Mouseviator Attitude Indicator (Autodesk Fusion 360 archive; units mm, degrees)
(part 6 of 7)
sketch "G1000" plane through (0, 0, 0) normal (0, 1, 0) x axis (1, 0, 0)
  line L1 (-258.3202, -84.4862) -> (-258.3202, -5.9899)
  line L2 (22.9166, -438.2961) -> (-83.2245, -438.2961)
  line L3 (113.9758, -58.4699) -> (-45.0242, -58.4699)
  line L4 (113.9758, -100.0333) -> (-45.0242, -100.0333)
  line L5 (500.0011, -95.2463) -> (-500.7967, -95.2463)
  curve K1 (500.0011, -306.3841) -> (185.0575, -438.1167)
  line L6 (200.3781, -200.5497) -> (-194.6385, -200.5497)
  line L7 (-194.6385, -95.2463) -> (-194.6385, -200.5497)
  line L8 (113.3594, -121.568) -> (109.2085, -117.4156)
  line L9 (-194.6385, -171.4463) -> (-266.0078, -171.4463)
  line L10 (-439.2563, -298.2055) -> (-439.2563, -260.1644)
  line L11 (-298.7965, -191.8326) -> (-387.2573, -191.8326)
  line L12 (-83.2245, -438.2961) -> (-183.5312, -438.2956)
  line L13 (-357.5866, -422.3558) -> (-360.6417, -421.6832)
  line L14 (113.9758, -58.4699) -> (113.9758, -100.0333)
  curve K2 (-183.5312, -438.2956) -> (-357.5866, -422.3558)
  line L15 (-464.0205, -260.1644) -> (-464.0205, -191.8326)
  line L16 (-279.0974, -84.4862) -> (-400.7939, -84.4862)
  line L17 (115.7849, -0.0004) -> (498.5011, -0.0004)
  line L18 (-266.0078, -171.4463) -> (-266.0078, -95.2463)
  line L19 (-258.3202, -5.9899) -> (-134.2963, -5.9899)
  line L20 (-400.7939, -5.9899) -> (-279.0974, -5.9899)
  line L21 (-134.2963, -84.4862) -> (-258.3202, -84.4862)
  line L22 (500.0011, -94.3924) -> (500.0011, -306.3841)
  line L23 (270.459, -171.4463) -> (200.3781, -171.4463)
  line L24 (-500.0066, -306.3725) -> (-500.0051, -94.4039)
  line L25 (-498.5077, 0.0037) -> (-115.1335, 0.0037)
  line L26 (-115.1335, -95.2463) -> (-115.1335, 0.0037)
  line L27 (-387.2573, -191.8326) -> (-387.2573, -260.1644)
  line L28 (-387.2573, -260.1644) -> (-387.2573, -298.2055)
  line L29 (-134.2963, -5.9899) -> (-134.2963, -84.4862)
  line L30 (-279.0974, -5.9899) -> (-279.0974, -84.4862)
  line L31 (-45.0242, -58.4699) -> (-45.0242, -100.0333)
  line L32 (200.3781, -95.2463) -> (200.3781, -200.5497)
  line L33 (-298.7965, -115.6858) -> (-298.7965, -191.8326)
  line L34 (185.0575, -438.1167) -> (22.9358, -438.2967)
  line L35 (-387.2573, -298.2055) -> (-439.2563, -298.2055)
  line L36 (270.459, -95.2463) -> (270.459, -171.4463)
  line L37 (-464.0205, -191.8326) -> (-464.0205, -115.6858)
  line L38 (-464.0205, -115.6858) -> (-298.7965, -115.6858)
  curve K3 (-360.6417, -421.6832) -> (-500.0066, -306.3725)
  line L39 (-439.2563, -260.1644) -> (-464.0205, -260.1644)
  line L40 (500.0011, -1.5017) -> (500.0011, -94.3924)
  line L41 (-500.0053, -91.3773) -> (-500.0076, -1.4963)
  line L42 (22.9358, -438.2967) -> (22.9166, -438.2961)
  line L43 (-121.7047, -438.2959) -> (-83.2245, -438.2961)
  line L44 (106.9943, -127.9308) -> (102.8434, -123.7784)
  line L45 (-400.7939, -84.4862) -> (-400.7939, -5.9899)
  line L46 (367.0685, -437.5413) -> (363.2394, -438.1232)
  line L47 (238.074, -152.3963) -> (238.074, -137.3483)
  line L48 (231.724, -137.3483) -> (231.724, -152.3963)
  line L49 (249.5325, -194.5335) -> (220.2654, -148.3591)
  line L50 (250.2362, -148.8204) -> (219.5617, -194.0721)
  line L51 (-227.2728, -171.4463) -> (-227.2728, -137.3483)
  line L52 (-233.6228, -137.3483) -> (-233.6228, -171.4463)
  line L53 (-215.8142, -194.5335) -> (-245.0814, -148.3591)
  line L54 (-215.1106, -148.8204) -> (-245.785, -194.0721)
  line L55 (115.7842, 0) -> (-115.7842, 0)
  line L56 (0, 20) -> (-69.9424, 20)
  curve K4 (-69.9424, 20) -> (-107.8843, 0)
  curve K5 (-104.8876, -0.1472) -> (-110.8811, 0.1472)
  curve K6 (-65.1162, 20) -> (-74.7686, 20)
  curve K7 (69.9424, 20) -> (107.8843, 0)
  curve K8 (104.8876, -0.1472) -> (110.8811, 0.1472)
  curve K9 (65.1162, 20) -> (74.7686, 20)
  line L57 (0, 20) -> (69.9424, 20)
  line L58 (-107.8843, 0) -> (-115.1335, 0.0037)
  line L59 (137.0775, -0.0004) -> (107.8843, 0)
  arc A1 centre (-269.8771, -5.9899) radius 2.1 clockwise from (-267.7771, -5.9899) to (-269.8771, -8.0899)
  arc A2 centre (-269.8771, -5.9899) radius 2.1 clockwise from (-271.9771, -5.9899) to (-269.8771, -3.8899)
  arc A3 centre (-269.8771, -5.9899) radius 2.1 clockwise from (-269.8771, -8.0899) to (-271.9771, -5.9899)
  arc A4 centre (-269.8771, -5.9899) radius 2.1 clockwise from (-269.8771, -3.8899) to (-267.7771, -5.9899)
  arc A5 centre (-227.862, -98.6221) radius 2 clockwise from (-227.862, -96.6221) to (-225.862, -98.6221)
  arc A6 centre (-227.862, -98.6221) radius 2 clockwise from (-227.862, -100.6221) to (-229.862, -98.6221)
  arc A7 centre (-181.0659, -98.81) radius 2 clockwise from (-179.0659, -98.81) to (-181.0659, -100.81)
  arc A8 centre (-181.0659, -98.81) radius 2 clockwise from (-183.0659, -98.81) to (-181.0659, -96.81)
  arc A9 centre (-227.862, -98.6221) radius 2 clockwise from (-225.862, -98.6221) to (-227.862, -100.6221)
  arc A10 centre (-181.0659, -98.81) radius 2 clockwise from (-181.0659, -96.81) to (-179.0659, -98.81)
  arc A11 centre (-181.0659, -98.81) radius 2 clockwise from (-181.0659, -100.81) to (-183.0659, -98.81)
  arc A12 centre (-227.862, -98.6221) radius 2 clockwise from (-229.862, -98.6221) to (-227.862, -96.6221)
  arc A13 centre (-121.301, -6.0097) radius 2.1 clockwise from (-121.301, -3.9097) to (-119.201, -6.0097)
  arc A14 centre (-121.301, -6.0097) radius 2.1 between (-119.201, -6.0097) and (-121.301, -3.9097)
  arc A15 centre (-48.3439, -154.7177) radius 39.5 clockwise from (-8.8439, -154.7177) to (-48.3439, -194.2177)
  arc A16 centre (-48.3439, -154.7177) radius 39.5 clockwise from (-48.3439, -115.2177) to (-8.8439, -154.7177)
  arc A17 centre (96.6497, -423.4584) radius 2 clockwise from (96.6497, -421.4584) to (98.6497, -423.4584)
  circle C1 centre (-1.5094, -33.2296) radius 9.4996
  arc A18 centre (-503.2298, -92.1309) radius 3.9528 between (-500.0049, -94.4168) and (-500.7967, -95.2463)
  circle C2 centre (53.0938, -31.4749) radius 9.4996
  arc A19 centre (11.7978, -121.8039) radius 2 clockwise from (9.7978, -121.8039) to (11.7978, -119.8039)
  arc A20 centre (364.1576, -96.9137) radius 2 clockwise from (364.1576, -98.9137) to (362.1576, -96.9137)
  arc A21 centre (-498.5057, -94.3868) radius 1.4995 between (-500.0049, -94.4168) and (-500.0051, -94.4039)
  arc A22 centre (-80.8736, -187.2354) radius 2 clockwise from (-80.8736, -189.2354) to (-82.8736, -187.2354)
  arc A23 centre (96.6497, -423.4584) radius 2 clockwise from (98.6497, -423.4584) to (96.6497, -425.4584)
  arc A24 centre (11.7982, -186.8394) radius 2 clockwise from (13.7982, -186.8394) to (11.7982, -188.8394)
  arc A25 centre (76.8578, -121.8042) radius 2 clockwise from (74.8578, -121.8042) to (76.8578, -119.8042)
  arc A26 centre (2.8026, -423.5469) radius 2 clockwise from (2.8026, -421.5469) to (4.8026, -423.5469)
  arc A27 centre (-91.1619, -423.5469) radius 2 clockwise from (-91.1619, -421.5469) to (-89.1619, -423.5469)
  arc A28 centre (96.6497, -423.4584) radius 2 clockwise from (96.6497, -425.4584) to (94.6497, -423.4584)
  arc A29 centre (11.7978, -121.8039) radius 2 clockwise from (13.7978, -121.8039) to (11.7978, -123.8039)
  arc A30 centre (-3.4743, -132.862) radius 2 between (-5.4743, -132.862) and (-3.4743, -134.862)
  arc A31 centre (-15.8137, -187.2355) radius 2 clockwise from (-15.8137, -189.2355) to (-17.8137, -187.2355)
  arc A32 centre (154.113, -96.9036) radius 2 clockwise from (156.113, -96.9036) to (154.113, -98.9036)
  arc A33 centre (154.113, -96.9036) radius 2 clockwise from (154.113, -94.9036) to (156.113, -96.9036)
  arc A34 centre (189.9388, -421.6038) radius 2 clockwise from (187.9388, -421.6038) to (189.9388, -419.6038)
  arc A35 centre (231.5818, -97.187) radius 2.6 clockwise from (231.5818, -94.587) to (234.1818, -97.187)
  arc A36 centre (-487.0364, -238.8595) radius 2 clockwise from (-487.0364, -236.8595) to (-485.0364, -238.8595)
  circle C3 centre (-466.931, -89.4937) radius 2.0955
  arc A37 centre (231.5818, -97.187) radius 2.6 clockwise from (228.9818, -97.187) to (231.5818, -94.587)
  arc A38 centre (-487.0364, -238.8595) radius 2 clockwise from (-487.0364, -240.8595) to (-489.0364, -238.8595)
  arc A39 centre (2.8026, -423.5469) radius 2 clockwise from (4.8026, -423.5469) to (2.8026, -425.5469)
  arc A40 centre (-182.3033, -193.4594) radius 2.6 clockwise from (-182.3033, -196.0594) to (-184.9033, -193.4594)
  arc A41 centre (-80.874, -122.1999) radius 2 clockwise from (-82.874, -122.1999) to (-80.874, -120.1999)
  arc A42 centre (-80.874, -122.1999) radius 2 clockwise from (-80.874, -124.1999) to (-82.874, -122.1999)
  arc A43 centre (-182.3033, -193.4594) radius 2.6 clockwise from (-182.3033, -190.8594) to (-179.7033, -193.4594)
  arc A44 centre (-363.8121, -105.149) radius 2.6 between (-366.4121, -105.149) and (-363.8121, -107.749)
  arc A45 centre (-363.8121, -105.149) radius 2.6 between (-363.8121, -107.749) and (-361.2121, -105.149)
  arc A46 centre (-121.301, -6.0097) radius 2.1 between (-121.301, -3.9097) and (-123.401, -6.0097)
  circle C4 centre (-126.381, -81.3909) radius 2.0955
  arc A47 centre (-48.3439, -154.7177) radius 39.5 clockwise from (-48.3439, -194.2177) to (-87.8439, -154.7177)
  arc A48 centre (-121.301, -6.0097) radius 2.1 between (-121.301, -8.1097) and (-119.201, -6.0097)
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  point P362 (-194.6385, -95.2463)
  point P353 (-194.6385, -171.4463)
  point P357 (200.3781, -95.2463)
  point P359 (270.459, -95.2463)
  point P212 (-115.1335, -95.2463)
  point P358 (200.3781, -171.4463)
  point P434 (220.2654, -148.3591)
  point P436 (220.2654, -148.3591)
  point P435 (249.5325, -194.5335)
  point P440 (249.5325, -194.5335)
  point P433 (219.5617, -194.0721)
  point P439 (219.5617, -194.0721)
  point P437 (250.2362, -148.8204)
  point P438 (250.2362, -148.8204)
  point P441 (234.899, -171.4463)
  point P449 (-245.0814, -148.3591)
  point P451 (-245.0814, -148.3591)
  point P450 (-215.8142, -194.5335)
  point P455 (-215.8142, -194.5335)
  point P448 (-245.785, -194.0721)
  point P454 (-245.785, -194.0721)
  point P452 (-215.1106, -148.8204)
  point P453 (-215.1106, -148.8204)
  point P456 (-230.4478, -171.4463)
  point P355 (-266.0078, -95.2463)
  point P457 (0, 0)
  point P463 (-69.9424, 20)
  point P461 (-65.1162, 20)
  point P467 (-107.8843, 0)
  point P473 (137.0775, -0.0004)
  point P23 (500.0011, -94.3924)
  point P166 (500.0011, -94.3924)
  point P268 (500.0011, -95.2463)
  perpendicular L5 L18
  coincident P362 L5
  perpendicular L5 L7
  coincident P353 L7
  perpendicular L7 L9
  perpendicular L6 L7
  coincident P357 L5
  perpendicular L5 L32
  coincident P359 L5
  perpendicular L5 L36
  coincident P212 L5
  perpendicular L5 L26
  coincident P358 L32
  coincident P434 P436
  coincident P435 P440
  coincident P433 P439
  coincident P437 P438
  midpoint L49 L50
  midpoint P441 L50
  parallel L47 L48
  coincident P449 P451
  coincident P450 P455
  coincident P448 P454
  coincident P452 P453
  midpoint L53 L54
  midpoint P456 L54
  parallel L51 L52
  coincident P355 L5
  parallel L17 L55
  midpoint L55 P457
  midpoint P463 K6
  coincident P461 L56
  midpoint P467 K5
  coincident L17 P473
  coincident P23 P166
  coincident P268 L22
  dimension "d375" diameter = 4.0132 (= "0.158")
  dimension "d391" distance L5 L9 = 76.2 (= "3")
  dimension "d392" distance L5 L25 = 95.25 (= "3.75")
  dimension "d393" diameter = 4.318 (= "0.17")
  dimension "d394" angle L49 L50 = 66.5 (= "Angular Dimension-2")
  dimension "d395" distance P435 P436 = 54.6684 (= "2.152301")
  dimension "d396" distance P433 P438 = 54.6684 (= "2.152301")
  dimension "d397" distance L47 L48 = 6.35 (= "0.25")
  dimension "d398" diameter = 4.318 (= "0.17")
  dimension "d399" angle L53 L54 = 66.5 (= "Angular Dimension-3")
  dimension "d400" distance P450 P451 = 54.6684 (= "2.152301")
  dimension "d401" distance P448 P453 = 54.6684 (= "2.152301")
  dimension "d402" distance L51 L52 = 6.35 (= "0.25")
sketch "STD Instrument Sketch" plane through (0, 0, 0) normal (0, 1, 0) x axis (1, 0, 0)
  line L1 (-627.8819, 630.2527) -> (-627.8819, 609.5027)
  line L2 (-646.7348, 294.9756) -> (-601.0179, 324.9522)
  line L3 (-263.2396, 553.1298) -> (-263.2396, 467.6616)
  line L4 (-597.9215, 642.1904) -> (-593.0005, 637.4232)
  line L5 (-662.3195, 637.7132) -> (-657.5523, 642.6341)
  line L6 (-398.0011, 490.1616) -> (-398.0011, 469.4116)
  line L7 (-595.098, 635.258) -> (-600.019, 640.0252)
  line L8 (-593.4443, 577.7923) -> (-598.2115, 572.8713)
  line L9 (-655.3872, 640.5366) -> (-660.1544, 635.6157)
  line L10 (-660.6658, 580.2475) -> (-655.7448, 575.4803)
  line L11 (-601.0163, 294.9779) -> (-646.7363, 324.9499)
  line L12 (-594.0492, 636.3406) -> (-598.9702, 641.1078)
  line L13 (-600.3766, 574.9688) -> (-595.6094, 579.8898)
  line L14 (-239.6664, 444.0884) -> (-286.8127, 491.2347)
  line L15 (-657.8423, 573.3151) -> (-662.7633, 578.0823)
  line L16 (-286.8127, 444.0884) -> (-239.6664, 491.2347)
  circle C1 centre (-429.432, 499.0925) radius 2.159
  circle C2 centre (-398.0011, 467.6616) radius 40.259
  circle C3 centre (-176.8796, 467.6616) radius 28.575
  circle C4 centre (-567.9963, 294.9779) radius 2.159
  arc A1 centre (-598.9702, 641.1078) radius 1.5073 clockwise from (-600.019, 640.0252) to (-597.9215, 642.1904)
  circle C5 centre (-596.451, 576.3218) radius 2.159
  circle C6 centre (-627.8819, 607.7527) radius 40.259
  circle C7 centre (-601.0179, 324.9522) radius 2.159
  circle C8 centre (-623.8763, 309.9639) radius 14.3289
  circle C9 centre (-522.2763, 324.9499) radius 2.159
  circle C10 centre (-601.0163, 294.9779) radius 2.159
  circle C11 centre (-366.5702, 499.0925) radius 2.159
  circle C12 centre (-659.3128, 639.1836) radius 2.159
  circle C13 centre (-200.4527, 444.0884) radius 2.159
  circle C14 centre (-263.2396, 467.6616) radius 33.3375
  circle C15 centre (-153.3064, 444.0884) radius 2.159
  arc A2 centre (-656.7936, 574.3977) radius 1.5073 clockwise from (-655.7448, 575.4803) to (-657.8423, 573.3151)
  arc A3 centre (-594.0492, 636.3406) radius 1.5073 clockwise from (-593.0005, 637.4232) to (-595.098, 635.258)
  circle C16 centre (-239.6664, 491.2347) radius 2.159
  arc A4 centre (-661.7145, 579.1649) radius 1.5073 clockwise from (-662.7633, 578.0823) to (-660.6658, 580.2475)
  circle C17 centre (-646.7363, 324.9499) radius 2.159
  circle C18 centre (-153.3064, 491.2347) radius 2.159
  circle C19 centre (-239.6664, 444.0884) radius 2.159
  circle C20 centre (-522.2763, 294.9779) radius 2.159
  circle C21 centre (-545.1363, 309.9639) radius 14.3289
  circle C22 centre (-286.8127, 444.0884) radius 2.159
  circle C23 centre (-646.7348, 294.9756) radius 2.159
  circle C24 centre (-659.3128, 576.3218) radius 2.159
  circle C25 centre (-286.8127, 491.2347) radius 2.159
  circle C26 centre (-596.451, 639.1836) radius 2.159
  circle C27 centre (-200.4527, 491.2347) radius 2.159
  arc A5 centre (-661.2369, 636.6644) radius 1.5073 clockwise from (-660.1544, 635.6157) to (-662.3195, 637.7132)
  arc A6 centre (-656.4697, 641.5854) radius 1.5073 clockwise from (-657.5523, 642.6341) to (-655.3872, 640.5366)
  circle C28 centre (-429.432, 436.2307) radius 2.159
  circle C29 centre (-263.2396, 467.6616) radius 28.575
  circle C30 centre (-567.9963, 324.9499) radius 2.159
  arc A7 centre (-599.294, 573.9201) radius 1.5073 clockwise from (-598.2115, 572.8713) to (-600.3766, 574.9688)
  circle C31 centre (-366.5702, 436.2307) radius 2.159
  arc A8 centre (-594.5268, 578.8411) radius 1.5073 clockwise from (-595.6094, 579.8898) to (-593.4443, 577.7923)
  point P6 (-263.2396, 467.6616)
  point P5 (-263.2396, 467.6616)
  point P9 (-263.2396, 467.6616)
  point P14 (-398.0011, 467.6616)
  point P4 (-239.6664, 491.2347)
  point P3 (-239.6664, 444.0884)
  point P18 (-239.6664, 491.2347)
  point P2 (-286.8127, 491.2347)
  point P16 (-286.8127, 491.2347)
  point P7 (-286.8127, 444.0884)
  point P13 (-286.8127, 444.0884)
  point P19 (-239.6664, 444.0884)
  point P24 (-646.7363, 324.9499)
  point P29 (-646.7363, 324.9499)
  point P22 (-601.0163, 294.9779)
  point P30 (-601.0163, 294.9779)
  point P21 (-601.0179, 324.9522)
  point P31 (-601.0179, 324.9522)
  point P23 (-646.7348, 294.9756)
  point P34 (-646.7348, 294.9756)
  point P27 (-623.8763, 309.9639)
  equal C1 C28
  equal C28 C31
  equal C11 C31
  concentric C14 C29
  midpoint P6 L16
  midpoint P5 L14
  coincident P6 P9
  vertical L3
  horizontal P5 P14
  coincident P4 C14
  coincident P3 C14
  coincident P4 P18
  coincident P2 P16
  coincident P7 P13
  coincident P3 P19
  equal C22 C25
  equal C16 C19
  equal C19 C22
  equal C13 C27
  equal C15 C18
  equal C13 C15
  coincident P24 P29
  coincident P22 P30
  coincident P21 P31
  coincident P23 P34
  midpoint L2 L11
  midpoint P27 L2
  equal C12 C24
  equal C5 C24
  equal C5 C26
  parallel L4 L7
  dimension "d378" diameter C29 = 57.15 (= "2.250")
  dimension "d379" diameter C14 = 66.675 (= "2.625")
  dimension "d380" angle L3 L16 = 45 (= "Angular Dimension-2")
  dimension "d381" angle L3 L14 = 45 (= "Angular Dimension-3")
  dimension "d382" diameter C16 = 4.318 (= "0.170")
  dimension "d383" diameter C17 = 4.318 (= "0.17")
  dimension "d384" diameter C30 = 4.318 (= "0.17")
  dimension "d385" angle L2 L11 = 66.5 (= "Angular Dimension-4")
  dimension "d377" value = 360 (= "C-Pattern1-Angle")
sketch "TRC" plane through (0, 0, 0) normal (0, 1, 0) x axis (1, 0, 0)
  line L1 (195.1068, 26.3104) -> (195.1068, -204.4571)
  line L2 (93.9085, 237.7682) -> (113.276, 217.4007)
  curve K1 (-171.8957, -225.7547) -> (-345.9512, -209.8159)
  line L3 (-147.7942, -124.9554) -> (-151.9451, -120.8031)
  line L4 (6.4912, -194.1569) -> (-41.5088, -194.1569)
  line L5 (-46.5088, -199.1569) -> (-46.5088, -210.1569)
  line L6 (-107.7477, -193.4069) -> (-178.4477, -193.4069)
  line L7 (-41.5088, -215.1569) -> (6.4912, -215.1569)
  line L8 (-46.5088, -199.1569) -> (-46.5088, -210.1569)
  line L9 (-486.8744, 212.5429) -> (-104.1504, 212.5429)
  line L10 (194.142, 141.9592) -> (34.1068, 141.9592)
  line L11 (193.6552, -225.7547) -> (34.5713, -225.7547)
  curve K2 (511.636, -93.8395) -> (196.6931, -225.5738)
  line L12 (194.1068, -205.4571) -> (34.1068, -205.4571)
  line L13 (511.6348, 110.9356) -> (511.636, -93.8395)
  line L14 (127.4181, 212.5429) -> (510.1343, 212.5429)
  line L15 (-56.4987, 243.6261) -> (79.7664, 243.6261)
  line L16 (450.1357, -118.4152) -> (450.1357, -112.4991)
  line L17 (234.72, 147.2928) -> (235.447, 147.2928)
  line L18 (391.5195, -90.9091) -> (232.5195, -90.9091)
  line L19 (391.5195, -172.9091) -> (232.5195, -172.9091)
  line L20 (391.5195, -89.9091) -> (232.5195, -89.9091)
  line L21 (243.72, 145.2952) -> (254.628, 145.2952)
  line L22 (-71.589, -225.7547) -> (-171.8957, -225.7547)
  line L23 (433.1357, -112.4991) -> (433.1357, -118.4152)
  line L24 (232.5195, -90.9091) -> (232.5195, -172.9091)
  line L25 (384.7789, 174.4303) -> (384.7789, 170.6554)
  line L26 (391.5195, -173.9091) -> (232.5195, -173.9091)
  line L27 (391.5195, -90.9091) -> (391.5195, -172.9091)
  line L28 (243.72, 168.2928) -> (243.72, 145.2952)
  line L29 (392.5195, -90.9091) -> (392.5195, -172.9091)
  line L30 (396.6953, 170.6554) -> (396.6953, 174.4303)
  line L31 (-55.9198, 72.3593) -> (-60.0706, 76.5116)
  line L32 (33.1068, -204.4571) -> (33.1068, 140.9592)
  line L33 (437.6347, 162.4429) -> (437.6347, 102.4429)
  line L34 (442.6347, 102.4429) -> (442.6347, 162.4429)
  line L35 (-49.5547, 78.7221) -> (-53.7055, 82.8744)
  line L36 (231.5195, -90.9091) -> (231.5195, -172.9091)
  line L37 (-55.9191, -27.7326) -> (-60.0699, -23.5803)
  line L38 (-49.5539, -21.3698) -> (-53.7048, -17.2175)
  line L39 (254.628, 145.2952) -> (254.628, 192.2904)
  line L40 (-183.0634, -21.3693) -> (-178.9126, -17.217)
  line L41 (236.447, 148.2928) -> (236.447, 190.2928)
  line L42 (233.72, 190.2928) -> (233.72, 148.2928)
  line L43 (511.6343, 211.0429) -> (511.6348, 113.9356)
  line L44 (-35.2142, 127.6485) -> (-35.2142, 197.6485)
  line L45 (-50.2142, 197.6485) -> (-50.2142, 127.6485)
  line L46 (-35.2142, 127.6485) -> (-35.2142, 197.6485)
  line L47 (-50.2142, 197.6485) -> (-50.2142, 127.6485)
  line L48 (-176.6983, -27.7321) -> (-172.5474, -23.5798)
  line L49 (249.174, 181.3097) -> (249.174, 169.2928)
  line L50 (-49.5539, -118.5897) -> (-53.7048, -114.4373)
  line L51 (-488.3718, -93.8334) -> (-488.3714, 110.9171)
  line L52 (234.72, 191.2928) -> (235.447, 191.2928)
  line L53 (251.901, 181.3097) -> (249.174, 181.3097)
  line L54 (320.2949, 166.6268) -> (320.2949, 164.5429)
  line L55 (322.2949, 164.5429) -> (322.2949, 166.6268)
  line L56 (249.174, 169.2928) -> (244.72, 169.2928)
  line L57 (251.901, 192.2904) -> (251.901, 181.3097)
  line L58 (253.628, 193.2904) -> (252.901, 193.2904)
  line L59 (-57.9642, 149.6485) -> (-57.9642, 175.6485)
  line L60 (11.4912, -210.1569) -> (11.4912, -199.1569)
  line L61 (-62.9642, 175.6485) -> (-62.9642, 149.6485)
  line L62 (31.5713, -225.7547) -> (-68.5894, -225.7547)
  line L63 (320.2949, 164.5429) -> (322.2949, 164.5429)
  curve K3 (-349.0063, -209.1433) -> (-488.3718, -93.8334)
  line L64 (-60.9642, 147.6485) -> (-59.9642, 147.6485)
  line L65 (-55.9191, -124.9525) -> (-60.0699, -120.8001)
  line L66 (6.4912, -194.1569) -> (-41.5088, -194.1569)
  line L67 (-59.9642, 177.6485) -> (-60.9642, 177.6485)
  line L68 (11.4912, -210.1569) -> (11.4912, -199.1569)
  line L69 (195.142, 140.9588) -> (195.1068, 29.3104)
  line L70 (-239.7973, -27.7321) -> (-243.9482, -23.5798)
  line L71 (-141.4291, -118.5926) -> (-145.5799, -114.4403)
  line L72 (-180.9727, -195.9319) -> (-180.9727, -213.3819)
  line L73 (-371.8644, 145.1156) -> (-371.8644, 173.3156)
  line L74 (-117.6185, 141.2365) -> (-117.6185, 136.6967)
  line L75 (-178.4477, -215.9069) -> (-107.7477, -215.9069)
  line L76 (-106.6185, 136.6967) -> (-106.6185, 141.2365)
  line L77 (-438.6764, 168.7234) -> (-446.0249, 161.375)
  line L78 (-488.3714, 113.9432) -> (-488.3744, 211.0428)
  line L79 (-383.3644, 173.3156) -> (-383.3644, 145.1156)
  line L80 (-105.2227, -213.3819) -> (-105.2227, -195.9319)
  line L81 (-386.7644, 145.1156) -> (-386.7644, 173.3156)
  line L82 (-233.4322, -21.3693) -> (-237.5831, -17.217)
  line L83 (-90.0082, 217.4007) -> (-70.6408, 237.7682)
  line L84 (-190.0647, 145.1156) -> (-190.0647, 173.3156)
  line L85 (-383.3644, 145.1156) -> (-371.8644, 145.1156)
  line L86 (-328.1344, 178.6558) -> (-328.1344, 183.1957)
  line L87 (-434.3576, 149.7077) -> (-427.0092, 157.0562)
  line L88 (-319.1484, 183.2248) -> (-319.1484, 178.685)
  line L89 (-359.1311, 183.2139) -> (-359.1311, 178.6741)
  line L90 (-398.2644, 145.1156) -> (-386.7644, 145.1156)
  line L91 (-204.9647, 145.1156) -> (-204.9647, 173.3156)
  line L92 (-299.1431, 183.2059) -> (-299.1431, 178.6661)
  line L93 (-398.2644, 173.3156) -> (-398.2644, 145.1156)
  line L94 (-386.7644, 173.3156) -> (-398.2644, 173.3156)
  line L95 (-371.8644, 173.3156) -> (-383.3644, 173.3156)
  line L96 (-216.4647, 173.3156) -> (-216.4647, 145.1156)
  line L97 (-339.1344, 183.1957) -> (-339.1344, 178.6558)
  line L98 (-288.1431, 178.6661) -> (-288.1431, 183.2059)
  line L99 (-348.1311, 178.6741) -> (-348.1311, 183.2139)
  line L100 (-248.1512, 178.6961) -> (-248.1512, 183.2359)
  line L101 (-201.5647, 173.3156) -> (-201.5647, 145.1156)
  line L102 (-308.1484, 178.685) -> (-308.1484, 183.2248)
  line L103 (-279.1456, 183.2336) -> (-279.1456, 178.6937)
  line L104 (-268.1456, 178.6937) -> (-268.1456, 183.2336)
  line L105 (-259.1512, 183.2359) -> (-259.1512, 178.6961)
  line L106 (-216.4647, 145.1156) -> (-204.9647, 145.1156)
  line L107 (-204.9647, 173.3156) -> (-216.4647, 173.3156)
  line L108 (-201.5647, 145.1156) -> (-190.0647, 145.1156)
  line L109 (-190.0647, 173.3156) -> (-201.5647, 173.3156)
  line L110 (-228.1427, 178.7397) -> (-228.1427, 183.2795)
  line L111 (-239.1427, 183.2795) -> (-239.1427, 178.7397)
  arc A1 centre (196.6068, 26.3104) radius 1.5 between (195.7776, 27.5604) and (195.1068, 26.3104)
  arc A2 centre (201.2268, 22.8501) radius 2 between (201.2268, 24.8501) and (199.2268, 22.8501)
  arc A3 centre (201.2268, 32.7601) radius 2 between (201.2268, 34.7601) and (199.2268, 32.7601)
  arc A4 centre (201.2268, 22.8501) radius 2 between (199.2268, 22.8501) and (201.2268, 20.8501)
  arc A5 centre (201.2268, 32.7601) radius 2 between (203.2268, 32.7601) and (201.2268, 34.7601)
  arc A6 centre (195.6118, 27.8104) radius 0.3 between (195.9118, 27.8104) and (195.7776, 28.0604)
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sketch "RSG G1000 Cutouts" plane through (0, 0, 0) normal (0, 1, 0) x axis (1, 0, 0)
  line L1 (290.7301, -407.7931) -> (-1.3415, -407.7931)
  line L2 (-27.7477, -411.3153) -> (-55.9477, -411.3153)
  line L3 (-55.9477, -212.6993) -> (-27.7477, -212.6993)
  line L4 (-81.3539, -217.2215) -> (-81.3539, -406.7931)
  line L5 (-58.9477, -408.3153) -> (-58.9477, -215.6993)
  line L6 (291.7301, -217.2215) -> (291.7301, -406.7931)
  line L7 (-374.4255, -216.2215) -> (-82.3539, -216.2215)
  line L8 (-82.3539, -407.7931) -> (-374.4255, -407.7931)
  line L9 (-375.4255, -406.7931) -> (-375.4255, -217.2215)
  line L10 (-2.3415, -406.7931) -> (-2.3415, -217.2215)
  line L11 (-24.7477, -215.6993) -> (-24.7477, -408.3153)
  line L12 (-1.3415, -216.2215) -> (290.7301, -216.2215)
  circle C1 centre (-377.6397, -237.0073) radius 1.6
  circle C2 centre (-377.6397, -387.0073) radius 1.6
  arc A1 centre (-374.4255, -217.2215) radius 1 clockwise from (-375.4255, -217.2215) to (-374.4255, -216.2215)
  arc A2 centre (-82.3539, -217.2215) radius 1 clockwise from (-82.3539, -216.2215) to (-81.3539, -217.2215)
  circle C3 centre (-78.6397, -237.0073) radius 1.6
  arc A3 centre (-374.4255, -406.7931) radius 1 clockwise from (-374.4255, -407.7931) to (-375.4255, -406.7931)
  arc A4 centre (-82.3539, -406.7931) radius 1 clockwise from (-81.3539, -406.7931) to (-82.3539, -407.7931)
  arc A5 centre (290.7301, -406.7931) radius 1 clockwise from (291.7301, -406.7931) to (290.7301, -407.7931)
  circle C4 centre (-5.0557, -387.0073) radius 1.6
  circle C5 centre (293.9443, -387.0073) radius 1.6
  arc A6 centre (-27.7477, -408.3153) radius 3 clockwise from (-24.7477, -408.3153) to (-27.7477, -411.3153)
  circle C6 centre (-5.0557, -237.0073) radius 1.6
  arc A7 centre (-55.9477, -408.3153) radius 3 clockwise from (-55.9477, -411.3153) to (-58.9477, -408.3153)
  arc A8 centre (-1.3415, -217.2215) radius 1 clockwise from (-2.3415, -217.2215) to (-1.3415, -216.2215)
  arc A9 centre (290.7301, -217.2215) radius 1 clockwise from (290.7301, -216.2215) to (291.7301, -217.2215)
  arc A10 centre (-27.7477, -215.6993) radius 3 clockwise from (-27.7477, -212.6993) to (-24.7477, -215.6993)
  arc A11 centre (-1.3415, -406.7931) radius 1 clockwise from (-1.3415, -407.7931) to (-2.3415, -406.7931)
  circle C7 centre (-78.6397, -387.0073) radius 1.6
  arc A12 centre (-55.9477, -215.6993) radius 3 clockwise from (-58.9477, -215.6993) to (-55.9477, -212.6993)
  circle C8 centre (293.9443, -237.0073) radius 1.6
  point P46 (-41.8477, -411.3153)
  midpoint L2 P46
sketch "My G1000" plane through (0, 0, 0) normal (0, 1, 0) x axis (1, 0, 0)
  line L1 (-57.1129, -216.2745) -> (-26.0982, -216.2745)
  line L2 (-11.5031, -407.9397) -> (-11.5031, -216.2745)
  line L3 (-57.1129, -407.9397) -> (-57.1129, -216.2745)
  line L4 (-365.1051, -216.2745) -> (-365.1051, -407.9397)
  line L5 (-11.5031, -216.2745) -> (282.8322, -216.2745)
  line L6 (-68.5085, -407.9397) -> (-68.5085, -216.2745)
  line L7 (-26.0982, -216.2745) -> (-26.0982, -407.9397)
  line L8 (-26.0982, -407.9397) -> (-57.1129, -407.9397)
  line L9 (282.8322, -216.2745) -> (282.8322, -407.9397)
  line L10 (282.8322, -407.9397) -> (-11.5031, -407.9397)
  line L11 (-68.5085, -216.2745) -> (-365.1051, -216.2745)
  line L12 (-365.1051, -407.9397) -> (-68.5085, -407.9397)
  arc A1 centre (15.481, -219.7746) radius 2 between (15.481, -217.7746) and (13.481, -219.7746)
  arc A2 centre (15.481, -219.7746) radius 2 between (17.481, -219.7746) and (15.481, -217.7746)
  point P20 (-41.6056, -407.9397)
  midpoint P20 L8
sketch "ELT HOBBS" plane through (0, 0, 0) normal (0, 1, 0) x axis (1, 0, 0)
  line L1 (302.1056, -408.2108) -> (332.1056, -408.2108)
  line L2 (302.1056, -358.2108) -> (302.1056, -408.2108)
  line L3 (332.1056, -358.2108) -> (302.1056, -358.2108)
  line L4 (333.3151, -362.2108) -> (303.3151, -362.2108)
  line L5 (303.3151, -362.2108) -> (303.3151, -404.2108)
  line L6 (384.8016, -371.8358) -> (348.8016, -394.5858)
  line L7 (348.8016, -394.5858) -> (384.8016, -394.5858)
  line L8 (333.3151, -404.2108) -> (333.3151, -362.2108)
  line L9 (302.1056, -408.2108) -> (332.1056, -358.2108)
  line L10 (332.1056, -408.2108) -> (332.1056, -358.2108)
  line L11 (303.3151, -404.2108) -> (333.3151, -404.2108)
  line L12 (333.3151, -362.2108) -> (303.3151, -404.2108)
  line L13 (303.3151, -362.2108) -> (333.3151, -404.2108)
  line L14 (332.1056, -408.2108) -> (302.1056, -358.2108)
  line L15 (348.8016, -371.8358) -> (348.8016, -394.5858)
  line L16 (348.8016, -371.8358) -> (384.8016, -394.5858)
  line L17 (384.8016, -394.5858) -> (384.8016, -371.8358)
  line L18 (388.8016, -383.2108) -> (344.8016, -383.2108)
  line L19 (384.8016, -371.8358) -> (348.8016, -371.8358)
  circle C1 centre (344.8016, -383.2108) radius 2.159
  circle C2 centre (302.1056, -358.2108) radius 1.5
  circle C3 centre (332.1056, -408.2108) radius 1.5
  circle C4 centre (388.8016, -383.2108) radius 2.159
  circle C5 centre (302.1056, -408.2108) radius 1.5
  circle C6 centre (332.1056, -358.2108) radius 1.5
  point P19 (366.8016, -383.2108)
  point P23 (344.8016, -383.2108)
  point P24 (344.8016, -383.2108)
  point P17 (388.8016, -383.2108)
  point P22 (388.8016, -383.2108)
  point P6 (318.3151, -383.2108)
  point P7 (302.1056, -358.2108)
  point P8 (302.1056, -358.2108)
  point P12 (317.1056, -383.2108)
  point P9 (332.1056, -358.2108)
  point P14 (332.1056, -358.2108)
  point P11 (302.1056, -408.2108)
  point P15 (302.1056, -408.2108)
  point P10 (332.1056, -408.2108)
  point P13 (332.1056, -408.2108)
  point P16 (384.8016, -371.8358)
  point P18 (348.8016, -371.8358)
  point P21 (348.8016, -394.5858)
  point P4 (303.3151, -362.2108)
  point P5 (333.3151, -362.2108)
  point P3 (303.3151, -404.2108)
  horizontal L7
  perpendicular L7 L15
  parallel L7 L19
  parallel L15 L17
  coincident P19 L16
  coincident P19 L6
  coincident P23 P24
  coincident P17 P22
  midpoint P19 L18
  horizontal L11
  perpendicular L5 L11
  parallel L4 L11
  parallel L5 L8
  coincident P6 L13
  coincident P6 L12
  horizontal L3
  perpendicular L3 L10
  parallel L1 L3
  parallel L2 L10
  coincident P7 P8
  coincident P12 L14
  coincident P12 L9
  horizontal P6 P12
  coincident P9 P14
  coincident P11 P15
  coincident P10 P13
  horizontal P6 P19
  dimension "d125_1" distance P16 P18 = 36
  dimension "d551" distance P18 P21 = 22.75
  dimension "d127_1" diameter C1 = 4.318 (= "0.17")
  dimension "d128_1" diameter C4 = 4.318 (= "0.17")
  dimension "d554" distance P22 P24 = 44
  dimension "d253" distance P4 P5 = 30
  dimension "d254" distance P3 P4 = 42
  dimension "d255" diameter C2 = 3
  dimension "d256" distance P9 P10 = 50
  dimension "d257" distance P8 P9 = 30
  dimension "d258" diameter C6 = 3
  dimension "d259" diameter C5 = 3
  dimension "d260" diameter C3 = 3
sketch "Blank Analog" plane through (0, 0, 0) normal (0, 1, 0) x axis (1, 0, 0)
  line L1 (-172.9706, -420) -> (0, -420)
  curve K1 (-172.9706, -420) -> (-500, -294.703)
  curve K2 (-500, -302.074) -> (-500, -287.3319)
  curve K3 (-81.7028, -420) -> (-264.2385, -420)
  line L2 (-500, 0) -> (-500, -294.703)
  line L3 (-107.8843, 0) -> (-500, 0)
  curve K4 (-69.9424, 20) -> (-107.8843, 0)
  curve K5 (-104.8876, -0.1472) -> (-110.8811, 0.1472)
  curve K6 (-65.1162, 20) -> (-74.7686, 20)
  line L4 (0, 20) -> (-69.9424, 20)
  line L5 (0, -25.9835) -> (0, 0)
  line L6 (0, -149.2611) -> (0, -25.9835)
  line L7 (0, 20) -> (0, -420)
  line L8 (0, 20) -> (69.9424, 20)
  curve K7 (69.9424, 20) -> (107.8843, 0)
  curve K8 (104.8876, -0.1472) -> (110.8811, 0.1472)
  curve K9 (65.1162, 20) -> (74.7686, 20)
  line L9 (107.8843, 0) -> (500, 0)
  line L10 (500, 0) -> (500, -294.703)
  curve K10 (172.9706, -420) -> (500, -294.703)
  curve K11 (500, -302.074) -> (500, -287.3319)
  curve K12 (81.7028, -420) -> (264.2385, -420)
  line L11 (172.9706, -420) -> (0, -420)
  point P2 (-69.9424, 20)
  point P4 (-65.1162, 20)
  point P6 (-107.8843, 0)
  point P11 (-172.9706, -420)
  point P14 (-81.7028, -420)
  point P5 (-500, -294.703)
  point P16 (-500, -287.3319)
  point P1 (0, 0)
  point P17 (0, 0)
  point P22 (69.9424, 20)
  point P3 (0, 20)
  point P23 (0, 20)
  point P28 (65.1162, 20)
  point P30 (500, -294.703)
  point P24 (107.8843, 0)
  point P7 (-500, 0)
  point P29 (500, 0)
  point P8 (-74.7686, 20)
  point P27 (74.7686, 20)
  point P9 (-110.8811, 0.1472)
  point P25 (110.8811, 0.1472)
  point P10 (0, -420)
  point P36 (0, -420)
  point P31 (172.9706, -420)
  point P12 (-104.8876, -0.1472)
  point P26 (104.8876, -0.1472)
  point P13 (-264.2385, -420)
  point P34 (264.2385, -420)
  point P35 (81.7028, -420)
  point P15 (-500, -302.074)
  point P33 (500, -302.074)
  point P32 (500, -287.3319)
  perpendicular L2 L3
  perpendicular L2 L4
  midpoint P2 K6
  coincident P4 L4
  midpoint P6 K5
  midpoint P11 K3
  coincident P14 L1
  midpoint P5 K2
  coincident P16 L2
  coincident P1 P17
  perpendicular L4 L5
  perpendicular L4 L6
  symmetric P2 L7 P22
  symmetric P3 L7 P23
  symmetric P4 L7 P28
  symmetric P5 L7 P30
  symmetric P6 L7 P24
  symmetric P7 L7 P29
  symmetric P8 L7 P27
  symmetric P9 L7 P25
  symmetric P10 L7 P36
  symmetric P11 L7 P31
  symmetric P12 L7 P26
  symmetric P13 L7 P34
  symmetric P14 L7 P35
  symmetric P15 L7 P33
  symmetric P16 L7 P32
  dimension "d861" distance L3 L4 = 20
  dimension "d862" distance L1 L3 = 420
sketch "Almost Shared Bottom" plane through (0, 0, 0) normal (0, 1, 0) x axis (1, 0, 0)
  line L1 (107.8843, 0) -> (-107.8843, 0)
  line L2 (0, 20) -> (69.9424, 20)
  line L3 (107.8843, 0) -> (500, 0)
  line L4 (0, 20) -> (-69.9424, 20)
  line L5 (176.0865, -27.0556) -> (176.0865, -23.2779)
  line L6 (183.7415, -23.2779) -> (183.7415, -29.4869)
  line L7 (183.7415, -29.4869) -> (190.7415, -29.4869)
  line L8 (171.4865, -69.6959) -> (171.4865, -66.0556)
  line L9 (154.9321, -66.0556) -> (171.4865, -66.0556)
  line L10 (296.8, -82.55) -> (296.8, -19.05)
  line L11 (154.9321, -27.0556) -> (154.9321, -66.0556)
  line L12 (183.7415, -69.6959) -> (171.4865, -69.6959)
  line L13 (190.7415, -63.4869) -> (190.7415, -29.4869)
  line L14 (154.9321, -27.0556) -> (176.0865, -27.0556)
  line L15 (461.9, -19.05) -> (461.9, -82.55)
  line L16 (183.7415, -63.4869) -> (183.7415, -69.6959)
  line L17 (176.0865, -23.2779) -> (183.7415, -23.2779)
  line L18 (190.7415, -63.4869) -> (183.7415, -63.4869)
  curve K1 (69.9424, 20) -> (107.8843, 0)
  curve K2 (104.8876, -0.1472) -> (110.8811, 0.1472)
  curve K3 (65.1162, 20) -> (74.7686, 20)
  curve K4 (69.9424, 20) -> (107.8843, 0)
  curve K5 (104.8876, -0.1472) -> (110.8811, 0.1472)
  curve K6 (65.1162, 20) -> (74.7686, 20)
  curve K7 (-69.9424, 20) -> (-107.8843, 0)
  curve K8 (-104.8876, -0.1472) -> (-110.8811, 0.1472)
  curve K9 (-65.1162, 20) -> (-74.7686, 20)
  line L19 (0, 20) -> (69.9424, 20)
  line L20 (455.55, -88.9) -> (303.15, -88.9)
  line L21 (303.15, -12.7) -> (455.55, -12.7)
  line L22 (0, 20) -> (0, -420)
  line L23 (500, 0) -> (500, -95.25)
  curve K10 (-69.9424, 20) -> (-107.8843, 0)
  curve K11 (-104.8876, -0.1472) -> (-110.8811, 0.1472)
  curve K12 (-65.1162, 20) -> (-74.7686, 20)
  line L24 (-107.8843, 0) -> (-500, 0)
  line L25 (0, 20) -> (-69.9424, 20)
  line L26 (-130.43, -95.25) -> (-130.43, 0)
  line L27 (4.42, -95.25) -> (-130.43, -95.25)
  line L28 (4.42, -95.25) -> (500, -95.25)
  circle C1 centre (-58.04, -56.2) radius 4
  circle C2 centre (191.7213, -19.8424) radius 1.905
  circle C3 centre (191.7213, -70.6424) radius 1.905
  circle C4 centre (191.7213, -19.8424) radius 1.905
  circle C5 centre (154.8913, -19.8424) radius 1.905
  circle C6 centre (154.8913, -19.8424) radius 1.905
  circle C7 centre (154.8913, -70.6424) radius 1.905
  circle C8 centre (191.7213, -70.6424) radius 1.905
  circle C9 centre (154.8913, -70.6424) radius 1.905
  circle C10 centre (154.8913, -19.8424) radius 1.905
  circle C11 centre (191.7213, -19.8424) radius 1.905
  circle C12 centre (154.8913, -70.6424) radius 1.905
  arc A1 centre (455.55, -82.55) radius 6.35 between (455.55, -88.9) and (461.9, -82.55)
  circle C13 centre (191.7213, -70.6424) radius 1.905
  circle C14 centre (154.8913, -19.8424) radius 1.905
  circle C15 centre (191.7213, -70.6424) radius 1.905
  arc A2 centre (303.15, -82.55) radius 6.35 between (296.8, -82.55) and (303.15, -88.9)
  arc A3 centre (303.15, -19.05) radius 6.35 between (303.15, -12.7) and (296.8, -19.05)
  circle C16 centre (-0.1314, -56.9243) radius 6.35
  circle C17 centre (270.7296, -71.3118) radius 2.54
  circle C18 centre (57.289, -56.9243) radius 9.525
  circle C19 centre (491.999, -8.001) radius 2.159
  circle C20 centre (270.7296, -34.5828) radius 2.54
  circle C21 centre (191.7213, -19.8424) radius 1.905
  arc A4 centre (455.55, -19.05) radius 6.35 between (461.9, -19.05) and (455.55, -12.7)
  circle C22 centre (11.0854, -11.4414) radius 1.27
  circle C23 centre (491.999, -85.217) radius 2.159
  circle C24 centre (154.8913, -70.6424) radius 1.905
  circle C25 centre (-121.8609, -85.217) radius 2.159
  circle C26 centre (-121.8609, -8.001) radius 2.159
  circle C27 centre (47.4937, -11.4414) radius 1.27
  circle C28 centre (29.2895, -11.4414) radius 2.54
  circle C29 centre (-58.04, -11.75) radius 4
  point P31 (-69.9424, 20)
  point P33 (-65.1162, 20)
  point P41 (-107.8843, 0)
  point P39 (500, 0)
  point P43 (-500, 0)
  point P35 (107.8843, 0)
  point P51 (69.9424, 20)
  point P32 (0, 20)
  point P42 (0, 20)
  point P44 (-74.7686, 20)
  point P65 (74.7686, 20)
  point P59 (65.1162, 20)
  point P40 (104.8876, -0.1472)
  point P63 (-104.8876, -0.1472)
  point P57 (-130.43, 0)
  point P22 (296.8, -88.9)
  point P82 (296.8, -88.9)
  point P68 (461.9, -88.9)
  point P76 (296.8, -12.7)
  point P99 (154.9321, -27.0556)
  point P64 (0, 0)
  point P19 (-58.04, -11.75)
  point P85 (-58.04, -56.2)
  point P66 (491.999, -85.217)
  midpoint P31 K9
  coincident P33 L4
  midpoint P41 K8
  symmetric P39 P43 L22
  symmetric P35 P41 L22
  symmetric P31 P51 L22
  symmetric P32 P42 L22
  symmetric P44 P65 L22
  symmetric P33 P59 L22
  symmetric P40 P63 L22
  coincident P57 L24
  coincident P22 P82
  coincident P82 L20
  coincident P82 L10
  tangent A2 L20
  tangent L10 A2
  coincident P68 L20
  coincident P68 L15
  tangent A1 L20
  tangent A1 L15
  equal A1 A2
  coincident P76 L10
  coincident P76 L21
  tangent L10 A3
  tangent A3 L21
  tangent A4 L21
  tangent L15 A4
  equal A3 A4
  equal C1 C29
  perpendicular L7 L13
  perpendicular L6 L7
  perpendicular L13 L17
  perpendicular L5 L17
  coincident P99 L11
  perpendicular L11 L14
  perpendicular L13 L18
  perpendicular L8 L9
  equal C22 C27
  midpoint P64 L1
  dimension "d863" distance L4 L24 = 20
  dimension "d864" distance P68 P82 = 165.1 (= "6.5")
  dimension "d865" distance P76 P82 = 76.2 (= "3")
  dimension "d866" radius A2 = 6.35 (= "0.25")
  dimension "d867" radius A3 = 6.35 (= "0.25")
  dimension "d868" distance L3 L21 = 12.7 (= "0.5")
  dimension "d869" distance L15 L23 = 38.1 (= "1.5")
  dimension "d870" diameter C18 = 19.05 (= "0.75")
  dimension "d871" diameter C16 = 12.7 (= "0.5")
  dimension "d872" diameter C1 = 8
  dimension "d873" distance P19 L4 = 31.75 (= "1.25")
  dimension "d874" distance P85 L4 = 76.2 (= "3")
  dimension "d875" diameter C28 = 5.08 (= "0.2")
  dimension "d876" diameter C22 = 2.54 (= "0.1")
  dimension "d877" distance P66 L23 = 8.001 (= "0.315")
sketch "Side Wings" plane through (0, 0, 0) normal (0, 1, 0) x axis (1, 0, 0)
  line L1 (525.7316, -110.9551) -> (520.7141, -110.955)
  line L2 (511.005, -224.0813) -> (525.7287, -224.0816)
  line L3 (520.32, -228.9584) -> (511.0057, -228.9584)
  line L4 (520.3202, -224.0815) -> (520.32, -232.0032)
  line L5 (525.7287, -224.0816) -> (525.7316, -107.4016)
  line L6 (520.7141, -110.955) -> (520.7148, -79.9338)
  line L7 (520.32, -294.692) -> (520.32, -232.0032)
  line L8 (520.7148, -79.9338) -> (500, -79.9338)
  line L9 (511.0057, -228.9584) -> (511.005, -224.0813)
  line L10 (-526.6736, -105.4918) -> (-522.3504, -105.4918)
  line L11 (-522.3504, -105.4918) -> (-522.3504, -79.9338)
  line L12 (-520.32, -294.692) -> (-520.32, -253.4337)
  line L13 (-520.32, -253.4337) -> (-520.32, -228.9584)
  line L14 (-513.7068, -224.0816) -> (-526.6736, -224.0816)
  line L15 (-513.7068, -228.9584) -> (-513.7068, -224.0816)
  line L16 (-520.32, -224.0816) -> (-520.32, -228.9584)
  line L17 (-526.6736, -224.1265) -> (-526.6736, -105.4918)
  line L18 (-522.3504, -79.9338) -> (-500, -79.9338)
  line L19 (-520.32, -228.9584) -> (-513.7068, -228.9584)
  line L20 (500, -294.692) -> (500, -79.9338)
  line L21 (-500, -294.692) -> (-500, -79.9338)
  line L22 (-520.32, -294.692) -> (-500, -294.692)
  line L23 (500, 0) -> (500, -79.9338)
  line L24 (-500, 0) -> (-500, -79.9338)
  line L25 (-497.5914, 0) -> (-500, 0)
  line L26 (-472.1914, 0) -> (-497.5914, 0)
  line L27 (474.6, 0) -> (500, 0)
  circle C1 centre (511.1752, -162.4838) radius 3.81
  arc A1 centre (509.464, -135.4622) radius 12.7 clockwise from (500, -126.9933) to (500, -143.9311)
  circle C2 centre (511.1752, -105.3338) radius 3.81
  circle C3 centre (511.1752, -213.2838) radius 3.81
  circle C4 centre (-511.1752, -105.3338) radius 3.81
  circle C5 centre (-511.1752, -162.4838) radius 3.81
  circle C6 centre (-512.0079, -186.5029) radius 10.795
  circle C7 centre (-511.1752, -213.2838) radius 3.81
  arc A2 centre (-508.5619, -139.6363) radius 15.875 clockwise from (-500, -153.0045) to (-500, -126.268)
  point P25 (520.32, -228.9584)
  point P17 (520.3202, -224.0815)
  point P12 (511.005, -224.0813)
  point P13 (511.005, -224.0813)
  point P6 (525.7287, -224.0816)
  point P9 (525.7287, -224.0816)
  point P45 (-511.1752, -213.2838)
  point P47 (-511.1752, -105.3338)
  point P48 (-511.1752, -79.9338)
  point P46 (-511.1752, -162.4838)
  point P43 (-520.32, -224.0816)
  point P24 (520.32, -294.692)
  point P49 (500, -294.692)
  point P10 (500, -79.9338)
  point P51 (500, 0)
  point P34 (-500, -79.9338)
  point P52 (-500, 0)
  point P53 (-497.5914, 0)
  point P54 (-472.1914, 0)
  point P55 (474.6, 0)
  coincident P25 L7
  perpendicular L3 L7
  coincident P17 L2
  perpendicular L2 L4
  coincident P12 P13
  coincident P6 P9
  vertical L13
  horizontal L19
  vertical L15
  horizontal L14
  vertical P45 P47
  midpoint P48 L18
  vertical P47 P48
  vertical P45 P46
  coincident P43 L14
  perpendicular L14 L16
  equal C5 C7
  equal C4 C5
  perpendicular L8 L20
  horizontal P24 P49
  perpendicular L18 L21
  perpendicular L12 L22
  perpendicular L8 L23
  perpendicular L18 L24
  perpendicular L24 L25
  perpendicular L24 L26
  perpendicular L23 L27
  dimension "d878" diameter A1 = 25.4 (= "1")
  dimension "d99" distance P47 L18 = 25.4 (= "1")
  dimension "d100" distance P45 L18 = 133.35 (= "5.25")
  dimension "d103" distance P46 P48 = 82.55 (= "3.25")
  dimension "d887" diameter C6 = 21.59 (= "0.85")
  dimension "d888" diameter C7 = 7.62 (= "0.30")
  dimension "d903" distance P10 P51 = 79.9338 (= "3.147")
  dimension "d904" distance P34 P52 = 79.9338 (= "3.147")
  dimension "d905" distance P53 P54 = 25.4 (= "1")
  dimension "d906" distance P51 P55 = 25.4 (= "1")
sketch "WIIINGS!" plane through (0, 0, 0) normal (0, 1, 0) x axis (1, 0, 0)
  line L1 (520.32, -294.692) -> (520.32, -232.0032)
  line L2 (520.7148, -79.9338) -> (500, -79.9338)
  line L3 (525.7316, -110.9551) -> (520.7141, -110.955)
  line L4 (-526.6736, -224.1265) -> (-526.6736, -105.4918)
  line L5 (511.005, -224.0813) -> (525.7287, -224.0816)
  line L6 (525.7287, -224.0816) -> (525.7316, -107.4016)
  line L7 (-522.3504, -79.9338) -> (-500, -79.9338)
  line L8 (520.7141, -110.955) -> (520.7148, -79.9338)
  line L9 (500, -294.692) -> (500, -79.9338)
  line L10 (-520.32, -228.9584) -> (-513.7068, -228.9584)
  line L11 (-513.7068, -228.9584) -> (-513.7068, -224.0816)
  line L12 (-520.32, -294.692) -> (-520.32, -253.4337)
  line L13 (-500, -294.692) -> (-500, -79.9338)
  line L14 (520.32, -228.9584) -> (511.0057, -228.9584)
  line L15 (-526.6736, -105.4918) -> (-522.3504, -105.4918)
  line L16 (-513.7068, -224.0816) -> (-526.6736, -224.0816)
  line L17 (-520.32, -224.0816) -> (-520.32, -228.9584)
  line L18 (-520.32, -253.4337) -> (-520.32, -228.9584)
  line L19 (-522.3504, -105.4918) -> (-522.3504, -79.9338)
  line L20 (511.0057, -228.9584) -> (511.005, -224.0813)
  line L21 (520.3202, -224.0815) -> (520.32, -232.0032)
  line L22 (-500.0066, -306.3725) -> (-500.0051, -94.4039)
  curve K1 (-360.6417, -421.6832) -> (-500.0066, -306.3725)
  line L23 (-357.5866, -422.3558) -> (-360.6417, -421.6832)
  curve K2 (-183.5312, -438.2956) -> (-357.5866, -422.3558)
  line L24 (-83.2245, -438.2961) -> (-183.5312, -438.2956)
  line L25 (22.9358, -438.2967) -> (22.9166, -438.2961)
  line L26 (185.0575, -438.1167) -> (22.9358, -438.2967)
  curve K3 (500.0011, -306.3841) -> (185.0575, -438.1167)
  line L27 (500.0011, -94.3924) -> (500.0011, -306.3841)
  line L28 (22.9166, -438.2961) -> (-83.2245, -438.2961)
  curve K4 (-365.1585, -441.4954) -> (-520.3266, -306.7926)
  line L29 (-361.7314, -442.2499) -> (-365.1585, -441.4954)
  curve K5 (-183.7895, -458.6156) -> (-361.7314, -442.2499)
  line L30 (-83.2246, -458.6161) -> (-183.7895, -458.6156)
  line L31 (22.5992, -458.6161) -> (-83.2246, -458.6161)
  line L32 (22.6296, -458.6171) -> (22.5992, -458.6161)
  line L33 (185.3185, -458.4364) -> (22.6296, -458.6171)
  curve K6 (520.3211, -306.7852) -> (185.3185, -458.4364)
  line L34 (520.3211, -224.0815) -> (520.3211, -306.7852)
  line L35 (-520.3266, -306.7926) -> (-520.326, -224.0816)
  circle C1 centre (511.1752, -213.2838) radius 3.81
  circle C2 centre (511.1752, -162.4838) radius 3.81
  arc A1 centre (509.464, -135.4622) radius 12.7 clockwise from (500, -126.9933) to (500, -143.9311)
  circle C3 centre (-512.0079, -186.5029) radius 10.795
  circle C4 centre (511.1752, -105.3338) radius 3.81
  circle C5 centre (-511.1752, -105.3338) radius 3.81
  circle C6 centre (-511.1752, -213.2838) radius 3.81
  circle C7 centre (-511.1752, -162.4838) radius 3.81
  arc A2 centre (-508.5619, -139.6363) radius 15.875 clockwise from (-500, -153.0045) to (-500, -126.268)
  point P23 (520.32, -228.9584)
  point P25 (520.3202, -224.0815)
  point P3 (511.005, -224.0813)
  point P4 (511.005, -224.0813)
  point P12 (525.7287, -224.0816)
  point P13 (525.7287, -224.0816)
  point P37 (-511.1752, -213.2838)
  point P38 (-511.1752, -105.3338)
  point P48 (-511.1752, -79.9338)
  point P41 (-511.1752, -162.4838)
  point P33 (-520.32, -224.0816)
  point P18 (520.32, -294.692)
  point P28 (500, -294.692)
  point P81 (520.3211, -224.0815)
  point P82 (-520.326, -224.0816)
  coincident P23 L1
  perpendicular L1 L14
  coincident P25 L5
  perpendicular L5 L21
  coincident P3 P4
  coincident P12 P13
  vertical L18
  horizontal L10
  vertical L11
  horizontal L16
  vertical P37 P38
  midpoint P48 L7
  vertical P38 P48
  vertical P37 P41
  coincident P33 L16
  perpendicular L16 L17
  equal C6 C7
  equal C5 C7
  perpendicular L2 L9
  horizontal P18 P28
  perpendicular L7 L13
  parallel L23 L29
  parallel L24 L30
  parallel L28 L31
  parallel L25 L32
  parallel L26 L33
  parallel L27 L34
  coincident L5 P81
  coincident L16 P82
  dimension "d896" diameter A1 = 25.4 (= "1")
  dimension "d897" distance P38 L7 = 25.4 (= "1")
  dimension "d898" distance P37 L7 = 133.35 (= "5.25")
  dimension "d899" distance P41 P48 = 82.55 (= "3.25")
  dimension "d900" diameter C3 = 21.59 (= "0.85")
  dimension "d901" diameter C6 = 7.62 (= "0.30")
